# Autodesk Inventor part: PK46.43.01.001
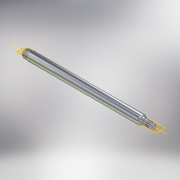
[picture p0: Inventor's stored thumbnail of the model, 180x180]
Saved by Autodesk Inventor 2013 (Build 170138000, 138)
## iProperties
Shininess: 64.0
Length Units: 11269
Angle Units: 11279
Time Units: 11290
Mass Units: 11283
Length Display Precision: 3
Angle Display Precision: 2
Compacted: True
Part Number: PK46.43.01.001
Document SubType Name: Modeling
Created: 2004-11
Material: Сталь высокопрочная низколегированная
Designer: ELarisa
Manufacturer: Standard
Standards Organization: Custom
Density: 7.84 g/cm^3
Density: 0.0
Volumn: 0.0
Area: 0.0
PropertySet Name: Model Information
Control State: 0
Master: False
Checked Out: False
Checked Out Date: 2008-10-09
Last Check In Date: 2008-10-09
Author: ELarisa
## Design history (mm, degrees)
sketch "Эскиз1"
  geometry: L1 (-25.116, -3.451)-(-25.116, 26.549); L2 (-25.116, 26.549)-(-23.116, 28.549); L3 (-23.116, 28.549)-(8.384, 28.549); L4 (8.384, 28.549)-(9.884, 27.049); L5 (9.884, 27.049)-(14.884, 27.049); L6 (17.482, 31.549)-(939.884, 31.549); L7 (939.884, 31.549)-(944.884, 30.21); L8 (944.884, 30.21)-(944.884, 18.549); L9 (944.884, 18.549)-(964.884, 18.549); L10 (964.884, 18.549)-(964.884, 16.699); L11 (964.884, 16.699)-(968.484, 16.699); L12 (968.484, 16.699)-(968.484, 18.549); L13 (968.484, 18.549)-(982.884, 18.549); L14 (982.884, 18.549)-(983.884, 17.549); L15 (983.884, 17.549)-(983.884, 16.049); L16 (983.884, 16.049)-(988.884, 16.049); L17 (988.884, 16.049)-(990.384, 17.549); L18 (990.384, 17.549)-(1019.884, 17.549); L19 (1019.884, 17.549)-(1021.884, 15.549); L20 (1021.884, 15.549)-(1021.884, 14.549); L21 (1021.884, 14.549)-(1042.384, 14.549); L22 (1042.384, 14.549)-(1043.884, 13.049); L23 (1043.884, 13.049)-(1043.884, -3.451); L24 (1043.884, -3.451)-(-25.116, -3.451); L25 (17.482, 31.549)-(14.884, 27.049)
  constraints: 50 end point, 17 parallel, 1 collinear, 1 perpendicular, 1 vertical
  dimensions: "d0" = 1069 distance of L23.end L1.start; "d3" = 135 deg angle of L3 L2; "d4" = 135 deg angle of L3 L4; "d6" = 18 distance between parallel lines of L24 L21; "d8" = 60 distance from line of L23 L14.end; "d9" = 99 distance between parallel lines of L23 L8; "d10" = 15 deg angle of L7 L6; "d11" = 5 horizontal distance of L6.end L7.end; "d12" = 20 distance from line of L10.end L8; "d13" = 3.6 distance of L10.end L11.end; "d14" = 5 distance of L15.end L16.end; "d15" = 135 deg angle of L16 L17; "d16" = 135 deg angle of L19 L18; "d17" = 135 deg angle of L14 L13 (derived); "d18" = 35 distance between parallel lines of L24 L6; "d19" = 32 distance between parallel lines of L24 L3; "d20" = 30.5 distance from line of L24 L4.end; "d21" = 22 distance between parallel lines of L24 L9; "d22" = 21 distance between parallel lines of L24 L18; "d23" = 19.5 distance between parallel lines of L24 L16; "d24" = 20.15 distance between parallel lines of L24 L11; "d25" = 135 deg angle of L22 L21 (derived); "d26" = 22 distance between parallel lines of L23 L20; "d27" = 1.5 horizontal distance of L22.end L21.end; "d28" = 2 horizontal distance of L19.end L18.end; "d29" = 1 horizontal distance of L13.end L14.end; "d30" = 2 horizontal distance of L1.end L2.end; "d43" = 5 distance of L4.end L5.end; "d44" = 60 deg angle of L6 L25; "d45" = 40 distance from line of L5.end L1
revolve "Вращение1" sketch "Эскиз1" stored, may be unused: angle "d31" = 90 deg
node "РабОсь1"
node "РабПлоскость1"
sketch "Эскиз2"
  geometry: L1 (-238.916, -3.451)-(1257.684, -3.451) reference; L2 (1043.884, -19.951)-(1043.884, 13.049) reference; C1 r 4 at (1029.884, -3.451)
  constraints: 1 centre point
  dimensions: "d33" = 0 distance from line of L1 C1.centre; "d34" = 14 distance from line of L2 C1.centre; "d37" = 8 diameter of C1
extrude "Выдавливание1" cut sketch "Эскиз2" stored distance "d35" = 10; taper "d36" = 0 deg
feature "Резьба1" dims "d38" = 10, "d39" = 0
feature "Резьба2" dims "d40" = 10, "d41" = 0
body "Solid1"
other parameters: "d32" = 18
